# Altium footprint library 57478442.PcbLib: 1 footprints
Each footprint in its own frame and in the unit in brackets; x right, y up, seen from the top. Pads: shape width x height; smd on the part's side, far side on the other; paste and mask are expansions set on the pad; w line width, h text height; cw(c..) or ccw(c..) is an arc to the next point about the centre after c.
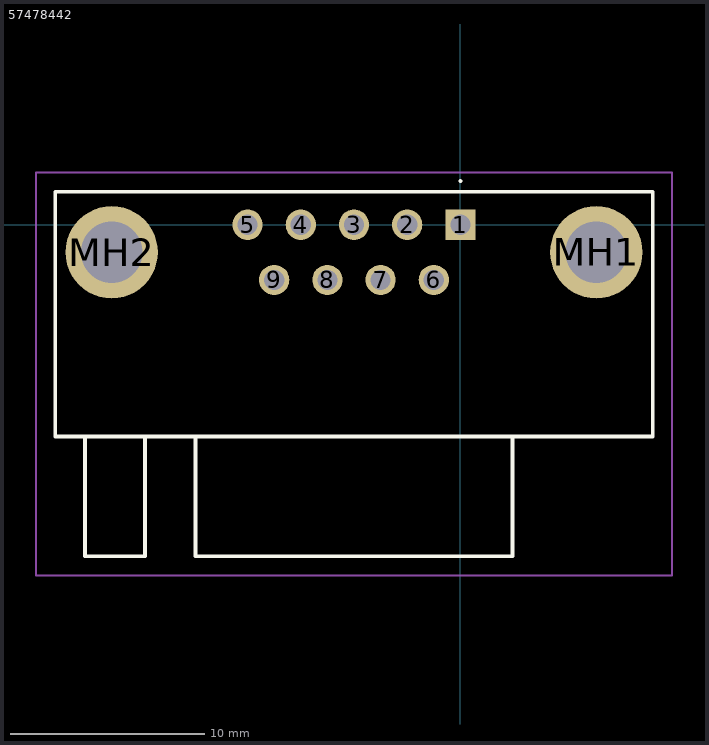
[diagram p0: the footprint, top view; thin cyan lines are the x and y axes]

## 57478442 [mil]
pads (11):
  rect 61.5x61.5 hole 41: 1(0,0)
  round 61.5 hole 41: 2(-107.99,0) 3(-215.98,0) 4(-324.02,0) 5(-432.01,0) 6(-54.02,-112.01) 7(-162.01,-112.01) 8(-270,-112.01) 9(-377.99,-112.01)
  round 187.48 hole 125: MH1(275.98,-55.98) MH2(-707.99,-55.98)
Top Overlay:
  lines w3.94: 0,86.61 0,86.61 ; 0,86.61 ccw(c0,88.58) 0,90.55 ; 0,86.61 cw(c0,88.58) 0,90.55 ; 0,90.55 0,90.55
  lines w7.87: -761.85,-430 -761.85,-672.99 -640.55,-672.99 -640.55,-430 ; -537.48,-430 -537.48,-672.99 105.51,-672.99 105.51,-430 ; -822.52,-430 -822.52,-187.01 -822.52,67.01 390.51,67.01 390.51,-187.01 390.51,-430 -822.52,-430
Mechanical 15:
  lines w3.94: -761.85,-430 -761.85,-672.99 -640.55,-672.99 -640.55,-430 ; -537.48,-430 -537.48,-672.99 105.51,-672.99 105.51,-430 ; -822.52,-430 390.51,-430 390.51,67.01 -822.52,67.01 -822.52,-430
Mechanical 20:
  lines w3.94: -861.89,-712.36 429.88,-712.36 429.88,106.38 -861.89,106.38 -861.89,-712.36
3D body "5747844-2.stp": height 228.35, standoff -183.07, extent -393.7,-132.9 393.7,132.9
